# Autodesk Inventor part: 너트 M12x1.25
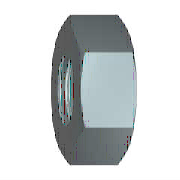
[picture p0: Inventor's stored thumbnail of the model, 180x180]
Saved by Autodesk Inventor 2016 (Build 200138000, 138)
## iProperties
IsCustomPart: 1
Created: 2012-02
Part Number: 너트 M12x1.25
Material: 강철, 연강
Description: 6각 너트
Document SubType Name: Modeling
Standard: KS B 1012
Designer: mduedu
Standards Organization: KS
Language: ko-KR
Size Designation: M12x1.25
Categories: <MemberInstance><Categories><Category DisplayName="조임쇠" InternalName="e4da775c-781d-43d5-af7c-5136215cf5a6" Mnemonic="FSTN"><Category DisplayName="너트" InternalN
Density: 1 g/cm^3
Appearance: 강철
Author: mduedu
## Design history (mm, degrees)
sketch "스케치1"
  geometry: L1 (-10.97, 0)-(-5.485, 9.5); L2 (-5.485, 9.5)-(5.485, 9.5); L3 (5.485, 9.5)-(10.97, 0); L4 (10.97, 0)-(5.485, -9.5); L5 (5.485, -9.5)-(-5.485, -9.5); L6 (-5.485, -9.5)-(-10.97, 0); 2 further points
  constraints: 12 end point, 1 coincident, 1 horizontal, 11 other
  dimensions: "d0" = 21.93931 distance of L3.end L1.start (= 1.1547 x SW)
extrude "본체" new body sketch "스케치1" distance "d1" = 10 (= KOH); taper "d2" = 0 deg
sketch "스케치2"
  geometry: L1 (0, 5.485)-(0, 10.97) reference; L2 (0, 10.97)-(10, 10.97) reference; L3 (10, 5.485)-(10, 10.97) reference; L4 (-2, 0)-(12, 0) reference; L5 (0.849, 10.97)-(0, 9.5); L6 (9.151, 10.97)-(10, 9.5)
  constraints: 4 end point, 4 point on line
  dimensions: "d3" = 30 deg angle of L1 L5 (= ANG1); "d4" = 30 deg angle of L3 L6 (= ANG2); "d5" = 19 diameter of L5.end L4 (= SW0); "d6" = 19 diameter of L6.end L4 (= SW01)
revolve "모따기1" sketch "스케치2" stored, may be unused: angle "d7" = 90 deg
sketch "스케치3"
  geometry: A1 r 9.5 centre (0, 0) between (-4.75, -8.227) and (4.75, -8.227) reference; 1 further point
  constraints: 1 coincident
hole "스레드" sketch "스케치3" at (0, 0) diameter "d25" = 10.647; stored, may be unused: countersink angle "d29" = 82 deg, drill point angle "d31" = 118 deg; dims "d26" = 6, "d27" = 4, "d28" = 2, "d30" = 8
workaxis "Work Axis1"
workplane "Work Plane1"
body "Solid1"
chamfer "모따기2" distance "d8" = 0.67658 (= -0.5 x GD1 + 0.5 x NND); stored, may be unused: angle "d9" = 30 deg, second distance "d40" = 0.67658 (= -0.5 x GD1 + 0.5 x NND)
chamfer "모따기3" distance "d10" = 0.67658 (= -0.5 x GD1 + 0.5 x NND); stored, may be unused: angle "d11" = 30 deg, second distance "d41" = 0.67658 (= -0.5 x GD1 + 0.5 x NND)
other parameters: "ANG1" = 30 deg [user parameter; used in 1 equation term], "ANG2" = 30 deg [user parameter; used in 1 equation term], "NND" = 12 [user parameter; used in 4 equation terms], "KOH" = 10 [user parameter; used in 1 equation term], "SW" = 19 [user parameter; used in 4 equation terms], "SW0" = 19 (= SW) [user parameter; used in 1 equation term], "SW01" = 19 (= SW) [user parameter; used in 1 equation term], "GD1" = 10.64684 (computed from THREADDIA, PTC, TOA) [user parameter; used in 4 equation terms], "d13" = 0, "d14" = 0, "d39" = 0, "d42" = 0, "GUL" = 0.67658 (= 0.541266 x PTC) [user parameter], "TPU" = 8 (computed from PTC) [user parameter], "THREADDIA" = 12 [user parameter; used in 1 equation term], "TOA" = 30 deg [user parameter; used in 1 equation term], "PTC" = 1.25 [user parameter; used in 4 equation terms], "E0" = 21.945 (= 1.155 x SW) [user parameter], "GAL" = 0.67658 (= 0.541266 x PTC) [user parameter]
